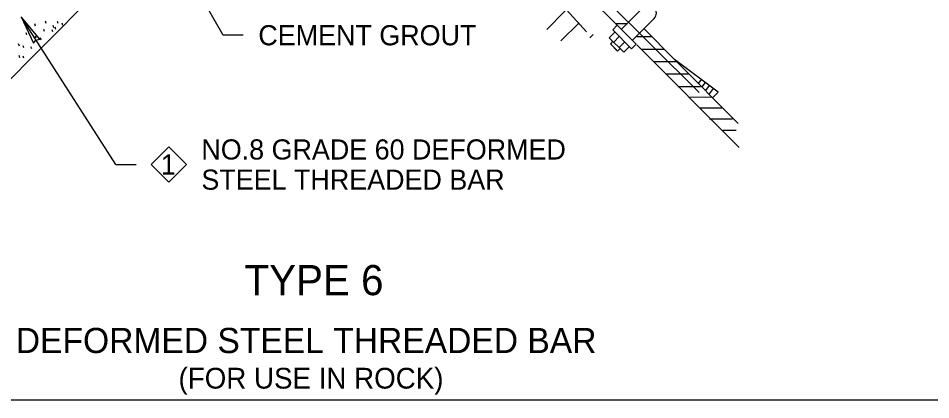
# Model space of a CAD drawing. Extents: x 99861 to 103151, y 100000 to 102076.
# Drawn here: x 101816 to 102542, y 100000 to 100303 of the extents above; entities that cross this region are included whole.
import ezdxf

# ---------------------------------------------------------------- set-up
doc = ezdxf.new("R2010")
doc.units = 0
for name, color, linetype in [('Level 1', 7, 'Continuous'), ('Level 10', 7, 'Continuous'), ('Level 15', 7, 'Continuous'), ('Level 18', 7, 'Continuous'), ('Level 2', 7, 'Continuous'), ('Level 20', 7, 'Continuous'), ('Level 28', 7, 'Continuous'), ('Level 4', 7, 'Continuous')]:
    doc.layers.add(name, color=color, linetype=linetype)

msp = doc.modelspace()

# ---------------------------------------------------------------- linework, layer by layer
at = {"layer": 'Level 1'}
for p, q in [((102292.7, 100297.38), (102260.42, 100329.66)), ((102389.53, 100200.56), (102307.94, 100282.14)), ((102388.77, 100219.5), (102337.86, 100270.41)), ((102372.61, 100244.5), (102368.24, 100240.03))]:
    msp.add_line(p, q, dxfattribs=at)
msp.add_lwpolyline([(99861, 100000), (103150, 100000), (103150, 102076), (99861, 102076)], close=True, dxfattribs=at)
msp.add_lwpolyline([(102372.61, 100244.5), (102337.86, 100270.41), (102313.71, 100295.02)], dxfattribs=at)
at = {"layer": 'Level 10'}
for p, q in [((102236.29, 100294.34), (102250.98, 100309.02)), ((102247.56, 100285.25), (102262.06, 100299.74)), ((102270.49, 100287.81), (102273.15, 100290.46)), ((102270.49, 100287.81), (102273.15, 100290.46))]:
    msp.add_line(p, q, dxfattribs=at)
at = {"layer": 'Level 15'}
for p, q in [((101994.77, 100289.76), (101978.77, 100289.76)), ((101893.44, 100186.95), (101909.44, 100186.95))]:
    msp.add_line(p, q, dxfattribs=at)
for points in [[(101978.77, 100289.76), (101978.77, 100289.76), (101922.43, 100387.76)], [(101893.44, 100186.95), (101893.44, 100186.95), (101817.93, 100304.25)]]:
    msp.add_lwpolyline(points, dxfattribs=at)
msp.add_lwpolyline([(101817.93, 100304.25), (101827.78, 100283.44), (101829.72, 100285.94), (101832.8, 100286.67)], close=True, dxfattribs=at)
at = {"layer": 'Level 2'}
for p, q in [((101889.84, 100335.95), (101767.98, 100213.25)), ((101829.4, 100297.05), (101828.83, 100298.8)), ((101836.57, 100292.68), (101836, 100294.42)), ((101837.83, 100299.21), (101837.26, 100300.95)), ((101843.2, 100292.42), (101842.63, 100294.17)), ((101844.05, 100295.64), (101843.47, 100297.39)), ((101845.72, 100294.33), (101845.15, 100296.08)), ((101847.54, 100299.01), (101846.97, 100300.76)), ((101851.23, 100297.52), (101850.66, 100299.26)), ((101822.62, 100290.04), (101822.04, 100291.78)), ((101829.98, 100287.33), (101829.41, 100289.07)), ((101833.91, 100285.89), (101833.34, 100287.64)), ((101816.55, 100281.12), (101815.98, 100282.86)), ((101820.24, 100279.62), (101819.67, 100281.37)), ((101826.37, 100278.84), (101825.8, 100280.58)), ((101816.94, 100271.84), (101816.37, 100273.59)), ((101820.22, 100271.41), (101819.64, 100273.16))]:
    msp.add_line(p, q, dxfattribs=at)
msp.add_lwpolyline([(102267.97, 100292.45), (102199.41, 100368.05), (102178.8, 100393), (102164.32, 100404.3)], dxfattribs=at)
at = {"layer": 'Level 20'}
msp.add_lwpolyline([(101935.48, 100200.99), (101949.52, 100186.95), (101935.48, 100172.91), (101921.44, 100186.95)], close=True, dxfattribs=at)
at = {"layer": 'Level 28'}
for p, q in [((102313.04, 100311.75), (102295.85, 100294.57)), ((102321.74, 100303.05), (102304.55, 100285.86)), ((102292.41, 100297.68), (102307.47, 100282.57)), ((102303.87, 100278.97), (102288.78, 100294.06)), ((102294.06, 100288.63), (102289.64, 100284.22)), ((102288.93, 100284.93), (102286.95, 100282.94)), ((102292.75, 100277.14), (102286.95, 100282.94)), ((102291.83, 100278.06), (102288.25, 100281.64)), ((102298.43, 100284.41), (102293.94, 100279.92)), ((102302.06, 100280.78), (102297.56, 100276.29)), ((102294.73, 100279.12), (102292.75, 100277.14))]:
    msp.add_line(p, q, dxfattribs=at)
for points in [[(102292.41, 100297.68), (102288.78, 100294.06)], [(102290.6, 100292.25), (102286.11, 100287.76), (102297.56, 100276.29)], [(102307.47, 100282.57), (102303.87, 100278.97)]]:
    msp.add_lwpolyline(points, dxfattribs=at)
msp.add_arc((102317.39, 100307.4), 6.15, 314.98343, 134.98343, dxfattribs=at)
at = {"layer": 'Level 4'}
for p, q in [((102357.51, 100244.15), (102034.01, 100566.65)), ((102290.72, 100299.13), (102300.63, 100299.14)), ((102308.1, 100288.62), (102319.98, 100288.64)), ((102311.52, 100278.72), (102329.67, 100278.75)), ((102321.21, 100268.84), (102339.37, 100268.87)), ((102330.91, 100258.95), (102349.07, 100258.98)), ((102359.4, 100254.75), (102356.81, 100251.44)), ((102362.41, 100252.1), (102359.82, 100248.8)), ((102340.6, 100249.07), (102358.76, 100249.1)), ((102365.56, 100249.76), (102362.56, 100245.93)), ((102368.87, 100247.29), (102365.56, 100243.06)), ((102349.56, 100240.64), (102367.37, 100240.67)), ((102357.8, 100232.05), (102375.55, 100232.07)), ((102365.85, 100223.35), (102384.02, 100223.38)), ((102376.56, 100214.22), (102387.09, 100214.23))]:
    msp.add_line(p, q, dxfattribs=at)

# ---------------------------------------------------------------- texts
at = {"layer": 'Level 18'}
for s, height, p in [('TYPE 6', 24, (101995.79, 100083.11)), ('DEFORMED STEEL THREADED BAR', 20, (101813.74, 100037.11)), ('(FOR USE IN ROCK)', 16.5, (101943.26, 100008.86))]:
    msp.add_text(s, height=height, dxfattribs=at).set_placement(p)
at = {"layer": 'Level 20'}
for s, p in [('CEMENT GROUT', (102006.77, 100281.76)), ('1', (101929.17, 100178.95))]:
    msp.add_text(s, height=16, dxfattribs=at).set_placement(p)
for s, p in [('NO.8 GRADE 60 DEFORMED', (101961.44, 100190.95)), ('STEEL THREADED BAR', (101961.44, 100166.95))]:
    msp.add_text(s, height=16, rotation=360, dxfattribs=at).set_placement(p)

doc.saveas('drawing.dxf')
